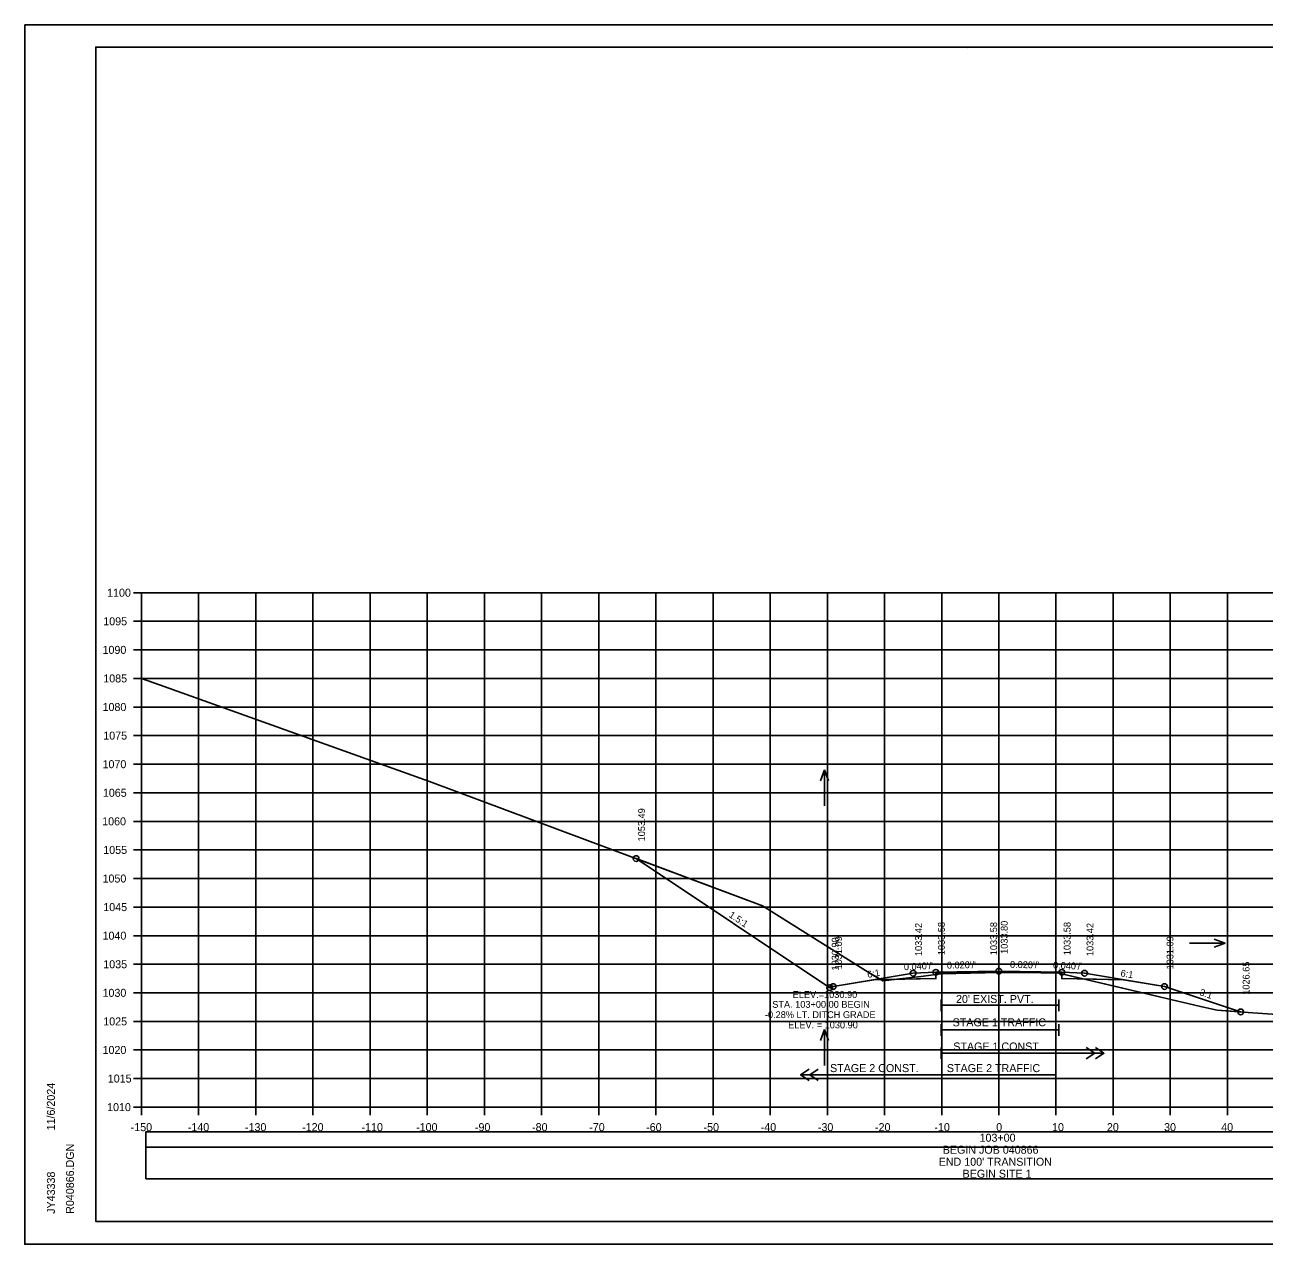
# Model space of a CAD drawing. Extents: x 1370565 to 1374448, y 301010 to 304637.
# Drawn here: x 1370564.6 to 1370781.5, y 301223.8 to 301437.2 of the extents above; entities that cross this region are included whole.
import ezdxf

# ---------------------------------------------------------------- set-up
doc = ezdxf.new("R2010")
doc.units = 0
for name, color, linetype in [('R_Alt Surface', 7, 'Continuous'), ('R_Axis', 7, 'Continuous'), ('R_Axis Annot', 7, 'Continuous'), ('R_Border', 7, 'Continuous'), ('R_Contours', 7, 'Continuous'), ('R_Drive', 7, 'Continuous'), ('R_Exist Surface', 7, 'Continuous'), ('R_Fin Surface', 7, 'Continuous'), ('R_Grid', 7, 'Continuous'), ('R_No Plot', 7, 'Continuous'), ('R_Water', 7, 'Continuous'), ('R_Water Annot', 7, 'Continuous'), ('R_Xsect Elev', 7, 'Continuous'), ('R_Xsect Slope', 7, 'Continuous')]:
    doc.layers.add(name, color=color, linetype=linetype)

msp = doc.modelspace()

# ---------------------------------------------------------------- linework, layer by layer
at = {"layer": 'R_Alt Surface'}
for points in [[(1370713.19, 301270.1), (1370724.03, 301270.31), (1370724.02, 301270.31), (1370724.03, 301271.23), (1370735.03, 301271.45), (1370746.03, 301271.23), (1370746.04, 301270.31), (1370746.03, 301270.31), (1370756.87, 301270.1)], [(1370724.97, 301266.63), (1370724.97, 301264.63)], [(1370724.97, 301265.63), (1370745.5, 301265.63)], [(1370745.5, 301266.63), (1370745.5, 301264.63)], [(1370724.97, 301262.31), (1370724.97, 301260.31)], [(1370724.97, 301261.31), (1370745.5, 301261.31)], [(1370745.5, 301262.31), (1370745.5, 301260.31)], [(1370724.93, 301258.25), (1370724.93, 301256.25)], [(1370750.32, 301258.25), (1370751.82, 301257.25), (1370750.32, 301256.25)], [(1370751.92, 301258.25), (1370753.42, 301257.25), (1370751.92, 301256.25)], [(1370724.93, 301257.25), (1370753.42, 301257.25)], [(1370701.84, 301254.46), (1370700.34, 301253.46), (1370701.84, 301252.46)], [(1370703.44, 301254.46), (1370701.94, 301253.46), (1370703.44, 301252.46)], [(1370725.03, 301254.46), (1370725.03, 301252.46)], [(1370745.03, 301254.46), (1370745.03, 301252.46)], [(1370700.34, 301253.46), (1370725.03, 301253.46)], [(1370725.03, 301253.46), (1370745.03, 301253.46)]]:
    msp.add_lwpolyline(points, dxfattribs=at)
at = {"layer": 'R_Axis'}
for p, q in [((1370583.63, 301337.81), (1370585.03, 301337.81)), ((1370585.03, 301247.81), (1370585.03, 301337.81)), ((1370583.63, 301332.81), (1370585.03, 301332.81)), ((1370583.63, 301327.81), (1370585.03, 301327.81)), ((1370583.63, 301322.81), (1370585.03, 301322.81)), ((1370583.63, 301317.81), (1370585.03, 301317.81)), ((1370583.63, 301312.81), (1370585.03, 301312.81)), ((1370583.63, 301307.81), (1370585.03, 301307.81)), ((1370583.63, 301302.81), (1370585.03, 301302.81)), ((1370583.63, 301297.81), (1370585.03, 301297.81)), ((1370583.63, 301292.81), (1370585.03, 301292.81)), ((1370583.63, 301287.81), (1370585.03, 301287.81)), ((1370583.63, 301282.81), (1370585.03, 301282.81)), ((1370583.63, 301277.81), (1370585.03, 301277.81)), ((1370583.63, 301272.81), (1370585.03, 301272.81)), ((1370583.63, 301267.81), (1370585.03, 301267.81)), ((1370583.63, 301262.81), (1370585.03, 301262.81)), ((1370583.63, 301257.81), (1370585.03, 301257.81)), ((1370583.63, 301252.81), (1370585.03, 301252.81)), ((1370583.63, 301247.81), (1370585.03, 301247.81)), ((1370585.03, 301247.81), (1370885.03, 301247.81)), ((1370585.03, 301246.41), (1370585.03, 301247.81)), ((1370595.03, 301246.41), (1370595.03, 301247.81)), ((1370605.03, 301246.41), (1370605.03, 301247.81)), ((1370615.03, 301246.41), (1370615.03, 301247.81)), ((1370625.03, 301246.41), (1370625.03, 301247.81)), ((1370635.03, 301246.41), (1370635.03, 301247.81)), ((1370645.03, 301246.41), (1370645.03, 301247.81)), ((1370655.03, 301246.41), (1370655.03, 301247.81)), ((1370665.03, 301246.41), (1370665.03, 301247.81)), ((1370675.03, 301246.41), (1370675.03, 301247.81)), ((1370685.03, 301246.41), (1370685.03, 301247.81)), ((1370695.03, 301246.41), (1370695.03, 301247.81)), ((1370705.03, 301246.41), (1370705.03, 301247.81)), ((1370715.03, 301246.41), (1370715.03, 301247.81)), ((1370725.03, 301246.41), (1370725.03, 301247.81)), ((1370735.03, 301246.41), (1370735.03, 301247.81)), ((1370745.03, 301246.41), (1370745.03, 301247.81)), ((1370755.03, 301246.41), (1370755.03, 301247.81)), ((1370765.03, 301246.41), (1370765.03, 301247.81)), ((1370775.03, 301246.41), (1370775.03, 301247.81))]:
    msp.add_line(p, q, dxfattribs=at)
at = {"layer": 'R_Border'}
for p, q in [((1370577.03, 301433.27), (1370893.21, 301433.27)), ((1370577.03, 301227.81), (1370577.03, 301433.27)), ((1370729.55, 301433.01), (1370729.55, 301433.01)), ((1370729.55, 301433.01), (1370729.55, 301433.01)), ((1370577.03, 301227.81), (1370577.03, 301227.81)), ((1370893.21, 301227.81), (1370577.03, 301227.81))]:
    msp.add_line(p, q, dxfattribs=at)
at = {"layer": 'R_Contours'}
for p, q in [((1370732.66, 301271.36), (1370724.03, 301271.23)), ((1370724.03, 301271.23), (1370724.03, 301271)), ((1370732.66, 301271.33), (1370735.03, 301271.39)), ((1370735.03, 301271.39), (1370732.66, 301271.36)), ((1370743.02, 301271.28), (1370735.03, 301271.39)), ((1370735.03, 301271.39), (1370743.02, 301271.28)), ((1370745.35, 301271.24), (1370743.02, 301271.28)), ((1370743.02, 301271.28), (1370745.35, 301271.24)), ((1370746.03, 301271.23), (1370745.5, 301271.24)), ((1370745.5, 301271.24), (1370746.03, 301271.11)), ((1370746.03, 301271.11), (1370746.03, 301271.23)), ((1370714.11, 301270.25), (1370713.19, 301270.1)), ((1370713.19, 301270.1), (1370714.32, 301270.12)), ((1370714.32, 301270.12), (1370714.11, 301270.25)), ((1370717.17, 301270.18), (1370714.32, 301270.12)), ((1370717.17, 301270.18), (1370724.03, 301270.31)), ((1370724.03, 301270.31), (1370724.03, 301271)), ((1370749.77, 301270.24), (1370746.03, 301271.11)), ((1370746.03, 301271.11), (1370746.04, 301270.31)), ((1370746.04, 301270.31), (1370749.77, 301270.24)), ((1370756.87, 301270.1), (1370749.77, 301270.24)), ((1370749.77, 301270.24), (1370770.29, 301265.44))]:
    msp.add_line(p, q, dxfattribs=at)
for points in [[(1370714.11, 301270.25), (1370711.72, 301271.74), (1370693.69, 301283.04), (1370671.57, 301291.3)], [(1370671.57, 301291.3), (1370705.45, 301268.71), (1370706.03, 301268.9), (1370713.19, 301270.1), (1370714.11, 301270.25)], [(1370724.03, 301271), (1370724.97, 301271.11), (1370732.66, 301271.33)], [(1370732.66, 301271.33), (1370732.66, 301271.36)], [(1370732.66, 301271.36), (1370732.66, 301271.33)], [(1370743.02, 301271.28), (1370743.02, 301271.28)], [(1370743.02, 301271.28), (1370743.02, 301271.28)], [(1370745.5, 301271.24), (1370745.5, 301271.24)], [(1370714.32, 301270.12), (1370714.71, 301269.88), (1370717.17, 301270.18)], [(1370724.03, 301271), (1370721.38, 301270.69), (1370717.17, 301270.18)], [(1370777.34, 301264.47), (1370764.03, 301268.9), (1370756.87, 301270.1)], [(1370770.29, 301265.44), (1370773.23, 301264.75), (1370777.34, 301264.47)]]:
    msp.add_lwpolyline(points, dxfattribs=at)
at = {"layer": 'R_Drive'}
for points in [[(1370585.82, 301240.8), (1370884.24, 301240.8), (1370884.24, 301243.5), (1370585.82, 301243.5)], [(1370585.82, 301235.27), (1370884.24, 301235.27), (1370884.24, 301240.8), (1370585.82, 301240.8)]]:
    msp.add_lwpolyline(points, close=True, dxfattribs=at)
at = {"layer": 'R_Exist Surface'}
msp.add_lwpolyline([(1370585.03, 301322.82), (1370588.17, 301321.7), (1370635.42, 301304.81), (1370693.69, 301283.04), (1370711.72, 301271.74), (1370714.71, 301269.88), (1370721.38, 301270.69), (1370724.97, 301271.11), (1370732.66, 301271.33), (1370735.03, 301271.39), (1370743.02, 301271.28), (1370745.5, 301271.24), (1370770.29, 301265.44), (1370773.23, 301264.75), (1370777.78, 301264.44), (1370817.58, 301261.66), (1370849.21, 301261.25), (1370867.01, 301261.03), (1370869.92, 301260.96), (1370878.14, 301260.88), (1370885.03, 301260.83)], dxfattribs=at)
at = {"layer": 'R_Fin Surface'}
msp.add_lwpolyline([(1370671.57, 301291.3), (1370705.45, 301268.71), (1370706.03, 301268.9), (1370720.03, 301271.24), (1370724.03, 301271.4), (1370735.03, 301271.62), (1370746.03, 301271.4), (1370750.03, 301271.24), (1370764.03, 301268.9), (1370777.34, 301264.47)], dxfattribs=at)
at = {"layer": 'R_Grid'}
for p, q in [((1370585.03, 301337.81), (1370885.03, 301337.81)), ((1370585.03, 301247.81), (1370585.03, 301337.81)), ((1370595.03, 301247.81), (1370595.03, 301337.81)), ((1370605.03, 301247.81), (1370605.03, 301337.81)), ((1370615.03, 301247.81), (1370615.03, 301337.81)), ((1370625.03, 301247.81), (1370625.03, 301337.81)), ((1370635.03, 301247.81), (1370635.03, 301337.81)), ((1370645.03, 301247.81), (1370645.03, 301337.81)), ((1370655.03, 301247.81), (1370655.03, 301337.81)), ((1370665.03, 301247.81), (1370665.03, 301337.81)), ((1370675.03, 301247.81), (1370675.03, 301337.81)), ((1370685.03, 301247.81), (1370685.03, 301337.81)), ((1370695.03, 301247.81), (1370695.03, 301337.81)), ((1370705.03, 301247.81), (1370705.03, 301337.81)), ((1370715.03, 301247.81), (1370715.03, 301337.81)), ((1370725.03, 301247.81), (1370725.03, 301337.81)), ((1370735.03, 301247.81), (1370735.03, 301337.81)), ((1370745.03, 301247.81), (1370745.03, 301337.81)), ((1370755.03, 301247.81), (1370755.03, 301337.81)), ((1370765.03, 301247.81), (1370765.03, 301337.81)), ((1370775.03, 301247.81), (1370775.03, 301337.81)), ((1370585.03, 301332.81), (1370885.03, 301332.81)), ((1370585.03, 301327.81), (1370885.03, 301327.81)), ((1370585.03, 301322.81), (1370885.03, 301322.81)), ((1370585.03, 301317.81), (1370885.03, 301317.81)), ((1370585.03, 301312.81), (1370885.03, 301312.81)), ((1370585.03, 301307.81), (1370885.03, 301307.81)), ((1370585.03, 301302.81), (1370885.03, 301302.81)), ((1370585.03, 301297.81), (1370885.03, 301297.81)), ((1370585.03, 301292.81), (1370885.03, 301292.81)), ((1370585.03, 301287.81), (1370885.03, 301287.81)), ((1370585.03, 301282.81), (1370885.03, 301282.81)), ((1370585.03, 301277.81), (1370885.03, 301277.81)), ((1370585.03, 301272.81), (1370885.03, 301272.81)), ((1370585.03, 301267.81), (1370885.03, 301267.81)), ((1370585.03, 301262.81), (1370885.03, 301262.81)), ((1370585.03, 301257.81), (1370885.03, 301257.81)), ((1370585.03, 301252.81), (1370885.03, 301252.81)), ((1370585.03, 301247.81), (1370885.03, 301247.81))]:
    msp.add_line(p, q, dxfattribs=at)
at = {"layer": 'R_No Plot'}
for p, q in [((1370564.63, 301437.17), (1370897.96, 301437.17)), ((1370564.63, 301223.84), (1370897.96, 301223.84))]:
    msp.add_line(p, q, dxfattribs=at)
for points in [[(1370564.62, 301437.17), (1370897.96, 301437.17), (1370897.96, 301223.83), (1370564.62, 301223.83)], [(1370810.95, 301433.27), (1370830.57, 301433.27), (1370830.57, 301423.39), (1370846.68, 301423.39), (1370869.88, 301423.39), (1370869.88, 301390.72), (1370893.09, 301390.72), (1370893.21, 301227.81), (1370577.03, 301227.81), (1370577.03, 301433.27)]]:
    msp.add_lwpolyline(points, close=True, dxfattribs=at)
for centre in [(1370671.57, 301291.3), (1370720.03, 301271.24), (1370724.03, 301271.4), (1370735.03, 301271.62), (1370746.03, 301271.4), (1370750.03, 301271.24), (1370705.45, 301268.71), (1370706.03, 301268.9), (1370764.03, 301268.9), (1370777.34, 301264.47)]:
    msp.add_circle(centre, 0.5, dxfattribs=at)
at = {"layer": 'R_Water Annot'}
for p, q in [((1370704.55, 301306.84), (1370703.85, 301304.91)), ((1370704.55, 301300.55), (1370704.55, 301306.84)), ((1370704.55, 301306.84), (1370705.25, 301304.91)), ((1370768.36, 301276.48), (1370774.64, 301276.48)), ((1370774.64, 301276.48), (1370772.72, 301277.18)), ((1370774.64, 301276.48), (1370772.72, 301275.78)), ((1370704.55, 301261.39), (1370703.85, 301259.47)), ((1370704.55, 301255.11), (1370704.55, 301261.39)), ((1370704.55, 301261.39), (1370705.25, 301259.47))]:
    msp.add_line(p, q, dxfattribs=at)
at = {"layer": 'R_Xsect Elev'}
msp.add_line((1370735.03, 301271.39), (1370735.03, 301281.39), dxfattribs=at)

# ---------------------------------------------------------------- texts
at = {"layer": 'R_Axis Annot'}
for s, p in [('1100', (1370579.02, 301337.11)), ('1095', (1370578.35, 301332.11)), ('1090', (1370578.22, 301327.11)), ('1085', (1370578.35, 301322.11)), ('1080', (1370578.22, 301317.11)), ('1075', (1370578.35, 301312.11)), ('1070', (1370578.22, 301307.11)), ('1065', (1370578.28, 301302.11)), ('1060', (1370578.16, 301297.11)), ('1055', (1370578.35, 301292.11)), ('1050', (1370578.22, 301287.11)), ('1045', (1370578.35, 301282.11)), ('1040', (1370578.22, 301277.11)), ('1035', (1370578.35, 301272.11)), ('1030', (1370578.22, 301267.11)), ("20' EXIST. PVT.", (1370727.54, 301266.03)), ('1025', (1370578.35, 301262.11)), ('1020', (1370578.22, 301257.11)), ('1015', (1370579.14, 301252.11)), ('1010', (1370579.02, 301247.11)), ('-150', (1370583.14, 301243.61)), ('-140', (1370593.14, 301243.61)), ('-130', (1370603.14, 301243.61)), ('-120', (1370613.14, 301243.61)), ('-110', (1370623.53, 301243.61)), ('-100', (1370633.08, 301243.61)), ('-90', (1370643.37, 301243.61)), ('-80', (1370653.37, 301243.61)), ('-70', (1370663.37, 301243.61)), ('-60', (1370673.33, 301243.61)), ('-50', (1370683.37, 301243.61)), ('-40', (1370693.37, 301243.61)), ('-30', (1370703.37, 301243.61)), ('-20', (1370713.37, 301243.61)), ('-10', (1370723.76, 301243.61)), ('103+00', (1370731.66, 301241.76)), ('0', (1370734.57, 301243.61)), ('10', (1370744.34, 301243.61)), ('20', (1370753.94, 301243.61)), ('30', (1370763.94, 301243.61)), ('40', (1370773.94, 301243.61)), ('BEGIN JOB 040866', (1370725.22, 301239.66)), ("END 100' TRANSITION", (1370724.51, 301237.56)), ('BEGIN SITE 1', (1370728.69, 301235.46))]:
    msp.add_text(s, height=1.4, dxfattribs=at).set_placement(p)
at = {"layer": 'R_Border'}
for s, p in [('11/6/2024', (1370569.89, 301243.74)), ('R040866.DGN', (1370573.22, 301229.14)), ('JY43338', (1370569.89, 301229.14))]:
    msp.add_text(s, height=1.4, rotation=90, dxfattribs=at).set_placement(p)
at = {"layer": 'R_Water'}
for s, p in [('STAGE 1 TRAFFIC', (1370726.95, 301261.95)), ('STAGE 1 CONST.', (1370727.06, 301257.72)), ('STAGE 2 CONST.', (1370705.5, 301253.94)), ('STAGE 2 TRAFFIC', (1370725.94, 301253.94))]:
    msp.add_text(s, height=1.4, dxfattribs=at).set_placement(p)
at = {"layer": 'R_Xsect Elev'}
for s, p in [('1053.49', (1370673.12, 301294.3)), ('1033.42', (1370721.58, 301274.24)), ('1033.58', (1370725.58, 301274.4)), ('1033.58', (1370734.73, 301274.39)), ('1033.80', (1370736.58, 301274.62)), ('1033.58', (1370747.58, 301274.4)), ('1033.42', (1370751.58, 301274.24)), ('1030.90', (1370707, 301271.71)), ('1031.09', (1370707.58, 301271.9)), ('1031.09', (1370765.58, 301271.9)), ('1026.65', (1370778.89, 301267.47))]:
    msp.add_text(s, height=1.2, rotation=90, dxfattribs=at).set_placement(p)
for s, p in [('ELEV.=1030.90', (1370698.97, 301266.91)), ('STA. 103+00.00 BEGIN ', (1370695.39, 301265.19)), ('-0.28% LT. DITCH GRADE', (1370694.11, 301263.39)), ('ELEV. = 1030.90', (1370698.18, 301261.59))]:
    msp.add_text(s, height=1.2, dxfattribs=at).set_placement(p)
at = {"layer": 'R_Xsect Slope'}
for s, rotation, p in [('1.5:1', 326.3086, (1370687.69, 301281.16)), ("0.020'/'", 1.1458, (1370725.95, 301272.04)), ('6:1', 9.4642, (1370712.1, 301270.42)), ("0.040'/'", 2.2906, (1370718.44, 301271.77)), ("0.020'/'", 358.8542, (1370736.98, 301272.18)), ("0.040'/'", 357.7094, (1370744.49, 301272.06)), ('6:1', 350.5358, (1370756.26, 301270.71)), ('3:1', 341.5651, (1370770.05, 301267.42))]:
    msp.add_text(s, height=1.2, rotation=rotation, dxfattribs=at).set_placement(p)

doc.saveas('drawing.dxf')
